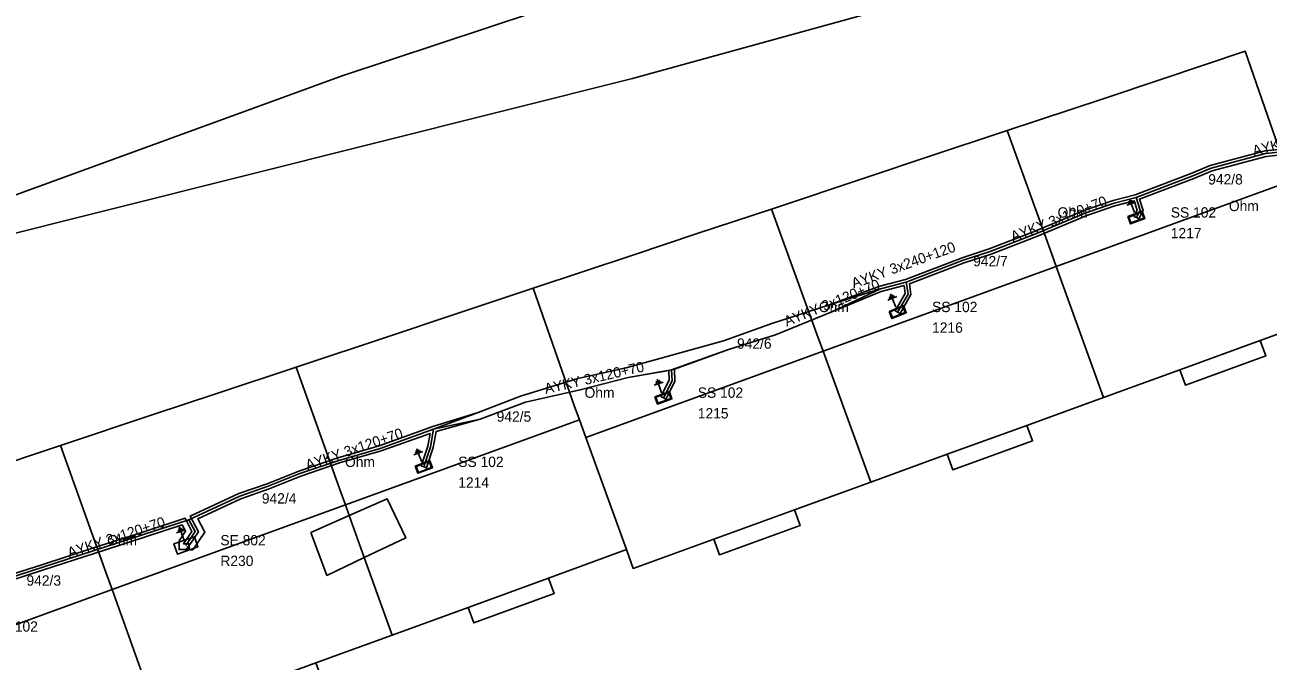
# Model space of a CAD drawing. Extents: x -793400 to -756198, y -1074141 to -1042963.
# Drawn here: x -783189.3 to -783099, y -1065161.1 to -1065114.9 of the extents above; entities that cross this region are included whole.
import ezdxf

# ---------------------------------------------------------------- set-up
doc = ezdxf.new("R2010")
doc.units = 0
for name, color, linetype in [('Parcela', 7, 'Continuous'), ('Popiskový text - Parcela', 7, 'Continuous'), ('Popiskový text - Přípojková skříň nn - SJZ', 7, 'Continuous'), ('Popiskový text - Přípojková skříň nn - Typ', 7, 'Continuous'), ('Popiskový text - Rozpojovací skříň nn - SJZ', 7, 'Continuous'), ('Popiskový text - Rozpojovací skříň nn - Typ', 7, 'Continuous'), ('Popiskový text - Uzemnění - Odpor', 7, 'Continuous'), ('Popiskový text - Vedení nn kabelové', 7, 'Continuous'), ('Skříň', 7, 'Continuous'), ('Spojnice nn', 7, 'Continuous'), ('Stavební objekt', 7, 'Continuous'), ('Uzemnění', 7, 'Continuous'), ('Vedení nn kabelové', 7, 'Continuous')]:
    doc.layers.add(name, color=color, linetype=linetype)

msp = doc.modelspace()

# ---------------------------------------------------------------- linework, layer by layer
at = {"layer": 'Parcela'}
for points in [[(-782898.51, -1065020.62), (-782948.33, -1065054.83), (-782960.53, -1065078.04), (-782969.74, -1065082.74), (-782972.88, -1065081.39), (-782979.27, -1065078.65), (-782999.34, -1065077.44), (-783019.03, -1065085.47), (-783022.01, -1065073.82), (-783037.89, -1065075.79), (-783069.1, -1065079.67), (-783093.52, -1065102.56), (-783130.63, -1065110.44), (-783148.72, -1065112.77), (-783166.26, -1065118.6), (-783200, -1065130.88), (-783236.01, -1065137.59), (-783242.83, -1065136.63), (-783249.82, -1065138.12)], [(-783065.04, -1065096.7), (-783145.19, -1065118.78), (-783192.44, -1065130.61), (-783216.76, -1065138.63), (-783235.89, -1065145.01), (-783239.65, -1065146.32), (-783242.83, -1065136.63), (-783236.01, -1065137.59), (-783200, -1065130.88), (-783166.26, -1065118.6), (-783148.72, -1065112.77), (-783130.63, -1065110.44), (-783093.52, -1065102.56)], [(-783192.44, -1065130.61), (-783145.19, -1065118.78), (-783065.04, -1065096.7)], [(-783097.85, -1065125.02), (-783100.7, -1065116.81), (-783106.77, -1065118.83), (-783111.03, -1065120.25), (-783117.99, -1065122.56), (-783123.81, -1065124.5), (-783128.09, -1065125.92), (-783135.11, -1065128.26), (-783140.56, -1065130.07), (-783145.1, -1065131.58), (-783152.41, -1065134.01), (-783158.36, -1065135.99), (-783162.69, -1065137.43), (-783169.61, -1065139.73), (-783175.43, -1065141.67), (-783179.99, -1065143.18), (-783186.71, -1065145.42), (-783192.52, -1065147.35)], [(-783168.19, -1065161.2), (-783162.65, -1065159.19), (-783157.12, -1065157.17), (-783156.71, -1065158.3), (-783150.87, -1065156.17), (-783151.29, -1065155.04), (-783145.63, -1065152.98), (-783145.14, -1065154.34), (-783139.28, -1065152.21), (-783138.88, -1065153.35), (-783133.02, -1065151.23), (-783133.44, -1065150.09), (-783127.89, -1065148.08), (-783122.35, -1065146.06), (-783121.94, -1065147.19), (-783116.14, -1065145.09), (-783116.55, -1065143.96), (-783111, -1065141.94), (-783105.45, -1065139.93), (-783105.05, -1065141.04), (-783099.21, -1065138.92), (-783099.61, -1065137.81), (-783093.94, -1065135.75)]]:
    msp.add_lwpolyline(points, dxfattribs=at)
for points in [[(-783099.21, -1065138.92), (-783105.05, -1065141.04), (-783105.45, -1065139.93), (-783111, -1065141.94), (-783114.44, -1065132.42), (-783114.87, -1065131.19), (-783117.99, -1065122.56), (-783111.03, -1065120.25), (-783106.77, -1065118.83), (-783100.7, -1065116.81), (-783097.85, -1065125.02), (-783097.43, -1065126.24), (-783093.94, -1065135.75), (-783099.61, -1065137.81)], [(-783116.14, -1065145.09), (-783121.94, -1065147.19), (-783122.35, -1065146.06), (-783127.89, -1065148.08), (-783131.35, -1065138.57), (-783131.8, -1065137.33), (-783135.11, -1065128.26), (-783128.09, -1065125.92), (-783123.81, -1065124.5), (-783117.99, -1065122.56), (-783114.87, -1065131.19), (-783114.44, -1065132.42), (-783111, -1065141.94), (-783116.55, -1065143.96)], [(-783133.02, -1065151.23), (-783138.88, -1065153.35), (-783139.28, -1065152.21), (-783145.14, -1065154.34), (-783145.63, -1065152.98), (-783148.58, -1065144.84), (-783149.04, -1065143.57), (-783149.42, -1065142.52), (-783152.41, -1065134.01), (-783145.1, -1065131.58), (-783140.56, -1065130.07), (-783135.11, -1065128.26), (-783131.8, -1065137.33), (-783131.35, -1065138.57), (-783127.89, -1065148.08), (-783133.44, -1065150.09)], [(-783150.87, -1065156.17), (-783156.71, -1065158.3), (-783157.12, -1065157.17), (-783162.65, -1065159.19), (-783164.66, -1065153.56), (-783165.75, -1065150.51), (-783166.03, -1065149.73), (-783166.44, -1065148.61), (-783169.61, -1065139.73), (-783162.69, -1065137.43), (-783158.36, -1065135.99), (-783152.41, -1065134.01), (-783149.42, -1065142.52), (-783149.04, -1065143.57), (-783148.58, -1065144.84), (-783145.63, -1065152.98), (-783151.29, -1065155.04)], [(-783167.78, -1065162.31), (-783173.64, -1065164.45), (-783174.04, -1065163.34), (-783179.58, -1065165.36), (-783182.97, -1065155.88), (-783183.4, -1065154.68), (-783186.71, -1065145.42), (-783179.99, -1065143.18), (-783175.43, -1065141.67), (-783169.61, -1065139.73), (-783166.44, -1065148.61), (-783166.03, -1065149.73), (-783165.75, -1065150.51), (-783164.66, -1065153.56), (-783162.65, -1065159.19), (-783168.19, -1065161.2)], [(-783184.72, -1065168.51), (-783190.57, -1065170.64), (-783190.98, -1065169.51), (-783196.68, -1065171.59), (-783197.15, -1065170.26), (-783200.06, -1065162.08), (-783200.51, -1065160.8), (-783200.9, -1065159.71), (-783203.94, -1065151.15), (-783196.87, -1065148.8), (-783192.52, -1065147.35), (-783186.71, -1065145.42), (-783183.4, -1065154.68), (-783182.97, -1065155.88), (-783179.58, -1065165.36), (-783185.13, -1065167.38)]]:
    msp.add_lwpolyline(points, close=True, dxfattribs=at)
at = {"layer": 'Skříň'}
for points in [[(-783109.235, -1065128.809), (-783108.178, -1065128.423), (-783107.985, -1065128.951), (-783109.041, -1065129.338)], [(-783108.212, -1065128.495), (-783109.163, -1065128.843), (-783109.008, -1065129.265), (-783108.057, -1065128.917)], [(-783126.567, -1065135.691), (-783125.525, -1065135.268), (-783125.313, -1065135.789), (-783126.355, -1065136.212)], [(-783125.556, -1065135.341), (-783126.494, -1065135.722), (-783126.324, -1065136.139), (-783125.386, -1065135.758)], [(-783143.574, -1065141.883), (-783142.513, -1065141.507), (-783142.326, -1065142.038), (-783143.386, -1065142.413)], [(-783142.548, -1065141.579), (-783143.502, -1065141.917), (-783143.352, -1065142.341), (-783142.398, -1065142.003)], [(-783160.965, -1065146.914), (-783159.912, -1065146.519), (-783159.714, -1065147.046), (-783160.768, -1065147.441)], [(-783159.945, -1065146.592), (-783160.893, -1065146.947), (-783160.735, -1065147.369), (-783159.787, -1065147.013)], [(-783176.994, -1065152.04), (-783178.483, -1065152.555), (-783178.226, -1065153.3), (-783176.737, -1065152.785)]]:
    msp.add_lwpolyline(points, close=True, dxfattribs=at)
at = {"layer": 'Spojnice nn'}
msp.add_line((-783127.18, -1065134.06), (-783125.31, -1065133.56), dxfattribs=at)
for points in [[(-783108.63, -1065127.42), (-783104.51, -1065125.85), (-783103.18, -1065125.29), (-783099.23, -1065124.24), (-783096.14, -1065123.92), (-783095.19, -1065124.7), (-783094.55, -1065126.4), (-783094.33, -1065127.45)], [(-783125.31, -1065133.56), (-783121.19, -1065131.98), (-783119.23, -1065131.34), (-783115.87, -1065130.04), (-783112.28, -1065128.53), (-783110.22, -1065127.84), (-783108.63, -1065127.42)], [(-783108.63, -1065127.42), (-783108.34, -1065128.35), (-783108.61, -1065128.88)], [(-783159.63, -1065144.24), (-783156.4, -1065143.03), (-783153.32, -1065141.83), (-783149.15, -1065140.57), (-783145.64, -1065139.79), (-783138.59, -1065137.82), (-783135.08, -1065136.57), (-783130.89, -1065135.2), (-783127.18, -1065134.06)], [(-783142.35, -1065139.94), (-783138.21, -1065138.46), (-783134.8, -1065137.39), (-783130.71, -1065135.73), (-783127.18, -1065134.06)], [(-783125.31, -1065133.56), (-783125.18, -1065134.43), (-783125.94, -1065135.74)], [(-783159.63, -1065144.24), (-783156.24, -1065143.52), (-783152.97, -1065142.28), (-783148.99, -1065141.37), (-783145.5, -1065140.49), (-783142.35, -1065139.94)], [(-783142.35, -1065139.94), (-783142.32, -1065140.73), (-783142.95, -1065141.96)], [(-783177.39, -1065150.81), (-783173.7, -1065149.1), (-783171.64, -1065148.38), (-783169.34, -1065147.46), (-783166.52, -1065146.5), (-783163.51, -1065145.63), (-783159.63, -1065144.24)], [(-783159.63, -1065144.24), (-783159.85, -1065145.52), (-783160.34, -1065146.98)], [(-783194.39, -1065156.57), (-783193.04, -1065156.06), (-783190.46, -1065155.05), (-783188.01, -1065154.26), (-783184.34, -1065153.06), (-783180.68, -1065151.89), (-783177.39, -1065150.81)], [(-783177.39, -1065150.81), (-783176.94, -1065151.67), (-783177.61, -1065152.67)]]:
    msp.add_lwpolyline(points, dxfattribs=at)
at = {"layer": 'Stavební objekt'}
for points in [[(-783105.45, -1065139.93), (-783111, -1065141.94), (-783114.44, -1065132.42), (-783097.43, -1065126.24), (-783093.94, -1065135.75), (-783099.61, -1065137.81)], [(-783122.35, -1065146.06), (-783127.89, -1065148.08), (-783131.35, -1065138.57), (-783114.44, -1065132.42), (-783111, -1065141.94), (-783116.55, -1065143.96)], [(-783139.28, -1065152.21), (-783145.14, -1065154.34), (-783145.63, -1065152.98), (-783148.58, -1065144.84), (-783131.35, -1065138.57), (-783127.89, -1065148.08), (-783133.44, -1065150.09)], [(-783148.58, -1065144.84), (-783145.63, -1065152.98), (-783151.29, -1065155.04), (-783157.12, -1065157.17), (-783162.65, -1065159.19), (-783164.66, -1065153.56), (-783161.65, -1065152.13), (-783163, -1065149.3), (-783165.75, -1065150.51), (-783166.03, -1065149.73), (-783149.04, -1065143.57)], [(-783168.55, -1065151.74), (-783167.38, -1065154.85), (-783164.66, -1065153.56), (-783162.65, -1065159.19), (-783168.19, -1065161.2), (-783174.04, -1065163.34), (-783179.58, -1065165.36), (-783182.97, -1065155.88), (-783166.03, -1065149.73), (-783165.75, -1065150.51)], [(-783190.98, -1065169.51), (-783196.68, -1065171.59), (-783197.15, -1065170.26), (-783200.06, -1065162.08), (-783182.97, -1065155.88), (-783179.58, -1065165.36), (-783185.13, -1065167.38)]]:
    msp.add_lwpolyline(points, close=True, dxfattribs=at)
at = {"layer": 'Uzemnění'}
for p, q in [((-783108.663, -1065127.749), (-783109.311, -1065127.99)), ((-783108.813, -1065127.706), (-783109.226, -1065127.86)), ((-783108.919, -1065127.639), (-783109.186, -1065127.739)), ((-783109.043, -1065127.572), (-783109.137, -1065127.607)), ((-783108.748, -1065128.511), (-783108.987, -1065127.869)), ((-783126.01, -1065134.61), (-783126.654, -1065134.861)), ((-783126.16, -1065134.569), (-783126.571, -1065134.73)), ((-783126.267, -1065134.504), (-783126.533, -1065134.608)), ((-783126.393, -1065134.438), (-783126.486, -1065134.475)), ((-783126.083, -1065135.373), (-783126.332, -1065134.735)), ((-783143.338, -1065140.638), (-783143.433, -1065140.67)), ((-783142.965, -1065140.828), (-783143.62, -1065141.047)), ((-783143.113, -1065140.78), (-783143.531, -1065140.92)), ((-783143.217, -1065140.71), (-783143.487, -1065140.8)), ((-783143.075, -1065141.587), (-783143.293, -1065140.937)), ((-783160.418, -1065145.85), (-783161.06, -1065146.106)), ((-783160.568, -1065145.811), (-783160.978, -1065145.974)), ((-783160.676, -1065145.746), (-783160.941, -1065145.852)), ((-783160.802, -1065145.682), (-783160.894, -1065145.719)), ((-783160.486, -1065146.614), (-783160.739, -1065145.978)), ((-783177.794, -1065151.493), (-783178.209, -1065151.641)), ((-783177.899, -1065151.425), (-783178.168, -1065151.52)), ((-783178.022, -1065151.355), (-783178.116, -1065151.388)), ((-783177.645, -1065151.538), (-783178.297, -1065151.769)), ((-783177.742, -1065152.299), (-783177.971, -1065151.654))]:
    msp.add_line(p, q, dxfattribs=at)
at = {"layer": 'Vedení nn kabelové'}
for points in [[(-783096.078, -1065123.712), (-783099.266, -1065124.043), (-783103.245, -1065125.1), (-783104.584, -1065125.664), (-783108.701, -1065127.233), (-783110.284, -1065127.65), (-783112.351, -1065128.343), (-783115.945, -1065129.854), (-783119.297, -1065131.152), (-783121.257, -1065131.791), (-783125.382, -1065133.373), (-783127.232, -1065133.867), (-783130.89, -1065135.2), (-783135.08, -1065136.57), (-783138.59, -1065137.82), (-783145.64, -1065139.79), (-783149.15, -1065140.57), (-783153.32, -1065141.83), (-783156.4, -1065143.03), (-783159.697, -1065144.052), (-783163.572, -1065145.44), (-783166.58, -1065146.309), (-783169.409, -1065147.272), (-783171.71, -1065148.193), (-783173.775, -1065148.914), (-783177.301, -1065150.548), (-783176.708, -1065151.683), (-783177.372, -1065152.675), (-783177.372, -1065152.977), (-783177.498, -1065152.977), (-783177.498, -1065152.848)], [(-783108.61, -1065128.88), (-783108.432, -1065128.971), (-783108.125, -1065128.368), (-783108.383, -1065127.54), (-783104.436, -1065126.036), (-783103.115, -1065125.48), (-783099.194, -1065124.437), (-783096.202, -1065124.128), (-783095.358, -1065124.821), (-783094.743, -1065126.456), (-783094.561, -1065127.323), (-783096.004, -1065127.863), (-783096.329, -1065128.289), (-783096.329, -1065128.711), (-783095.988, -1065128.711), (-783095.988, -1065128.499)], [(-783125.94, -1065135.74), (-783125.767, -1065135.84), (-783124.972, -1065134.47), (-783125.088, -1065133.689), (-783121.123, -1065132.169), (-783119.163, -1065131.528), (-783115.795, -1065130.225), (-783112.209, -1065128.717), (-783110.163, -1065128.032), (-783108.764, -1065127.662), (-783108.555, -1065128.332), (-783108.788, -1065128.789), (-783108.61, -1065128.88)], [(-783142.95, -1065141.96), (-783142.772, -1065142.051), (-783142.118, -1065140.775), (-783142.153, -1065139.869), (-783138.21, -1065138.46), (-783134.8, -1065137.39), (-783130.71, -1065135.73), (-783127.128, -1065134.253), (-783125.475, -1065133.811), (-783125.388, -1065134.39), (-783126.113, -1065135.64), (-783125.94, -1065135.74)], [(-783160.34, -1065146.98), (-783160.15, -1065147.044), (-783159.655, -1065145.569), (-783159.454, -1065144.4), (-783156.24, -1065143.52), (-783152.97, -1065142.28), (-783148.99, -1065141.37), (-783145.5, -1065140.49), (-783142.549, -1065139.975), (-783142.522, -1065140.685), (-783143.128, -1065141.869), (-783142.95, -1065141.96)], [(-783177.548, -1065152.848), (-783177.548, -1065153.004), (-783177.112, -1065153.004), (-783176.243, -1065151.708), (-783176.752, -1065150.735), (-783173.625, -1065149.286), (-783171.57, -1065148.567), (-783169.271, -1065147.648), (-783166.46, -1065146.691), (-783163.448, -1065145.82), (-783159.885, -1065144.544), (-783160.044, -1065145.471), (-783160.53, -1065146.916), (-783160.34, -1065146.98)], [(-783194.15, -1065158.93), (-783193.957, -1065158.982), (-783193.671, -1065157.912), (-783193.863, -1065157.37), (-783194.13, -1065156.686), (-783192.968, -1065156.247), (-783190.393, -1065155.238), (-783187.948, -1065154.45), (-783184.279, -1065153.25), (-783180.618, -1065152.08), (-783177.874, -1065151.179), (-783177.637, -1065151.632), (-783178.108, -1065152.336), (-783178.108, -1065152.977), (-783177.523, -1065152.977), (-783177.523, -1065152.848)], [(-783190.527, -1065154.862), (-783188.072, -1065154.07), (-783184.402, -1065152.87), (-783180.742, -1065151.7), (-783177.677, -1065150.694), (-783177.172, -1065151.657), (-783177.776, -1065152.559), (-783177.391, -1065152.559), (-783177.391, -1065152.775), (-783177.498, -1065152.775), (-783177.498, -1065152.76)]]:
    msp.add_lwpolyline(points, dxfattribs=at)

# ---------------------------------------------------------------- texts
at = {"layer": 'Popiskový text - Parcela'}
for s, p in [('942/8', (-783103.393, -1065126.478)), ('942/7', (-783120.459, -1065132.415)), ('942/6', (-783137.602, -1065138.396)), ('942/5', (-783155.052, -1065143.695)), ('942/4', (-783172.101, -1065149.636)), ('942/3', (-783189.187, -1065155.595))]:
    msp.add_text(s, height=0.75, dxfattribs=at).set_placement(p)
at = {"layer": 'Popiskový text - Přípojková skříň nn - SJZ'}
for s, p in [('1217', (-783106.11, -1065130.38)), ('1216', (-783123.44, -1065137.24)), ('1215', (-783140.45, -1065143.46)), ('1214', (-783157.84, -1065148.48))]:
    msp.add_text(s, height=0.75, dxfattribs=at).set_placement(p)
at = {"layer": 'Popiskový text - Přípojková skříň nn - Typ'}
for p in [(-783106.11, -1065128.88), (-783123.44, -1065135.74), (-783140.45, -1065141.96), (-783157.84, -1065146.98), (-783191.65, -1065158.93)]:
    msp.add_text('SS 102', height=0.75, dxfattribs=at).set_placement(p)
at = {"layer": 'Popiskový text - Rozpojovací skříň nn - SJZ'}
msp.add_text('R230', height=0.75, dxfattribs=at).set_placement((-783175.11, -1065154.17))
at = {"layer": 'Popiskový text - Rozpojovací skříň nn - Typ'}
msp.add_text('SE 802', height=0.75, dxfattribs=at).set_placement((-783175.11, -1065152.67))
at = {"layer": 'Popiskový text - Uzemnění - Odpor'}
for p in [(-783102.17, -1065128.41), (-783114.61, -1065128.88), (-783131.94, -1065135.74), (-783148.95, -1065141.96), (-783166.34, -1065146.98), (-783183.61, -1065152.67)]:
    msp.add_text(' Ohm', height=0.75, dxfattribs=at).set_placement(p)
at = {"layer": 'Popiskový text - Vedení nn kabelové'}
for s, rotation, p in [('AYKY 3x120+70', 14.8969, (-783100.067, -1065124.411)), ('AYKY 3x120+70', 21.14214, (-783117.557, -1065130.639)), ('AYKY 3x240+120', 19.99623, (-783129.13, -1065134.026)), ('AYKY 3x120+70', 22.11617, (-783134, -1065136.796)), ('AYKY 3x120+70', 12.89155, (-783151.492, -1065141.686)), ('AYKY 3x120+70', 18.79302, (-783168.782, -1065147.217)), ('AYKY 3x120+70', 18.10547, (-783186.071, -1065153.573))]:
    msp.add_text(s, height=0.75, rotation=rotation, dxfattribs=at).set_placement(p)

doc.saveas('drawing.dxf')
